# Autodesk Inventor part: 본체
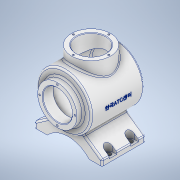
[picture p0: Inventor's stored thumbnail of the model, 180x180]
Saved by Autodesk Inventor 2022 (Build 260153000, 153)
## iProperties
Created: 2023-04
Part Number: 본체
Material: 알루미늄 6061
Document SubType Name: Modeling
Designer: Admin
Mass: 1296.38 g
Surface Area: 1061.17 cm^2
Volume: 480.141 cm^3
Density: 2.7 g/cm^3
Appearance: 알루미늄 - 평지
Author: Admin
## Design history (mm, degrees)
sketch "스케치5"
  geometry: L1 (0, -10.683)-(0, 64.095) reference; L2 (-86.8, 0)-(86.8, 0) reference; L3 (-62, 0)-(-62, 10); L4 (-62, 10)-(0, 53.413); L5 (0, 53.413)-(62, 10); L6 (62, 10)-(62, 0); L7 (-62, 0)-(62, 0); 1 further point
  constraints: 10 end point, 3 point on line, 2 perpendicular, 1 vertical
  dimensions: "d21" = 10 distance of L5.end L6.end; "d22" = 10 distance of L3.start L3.end; "d23" = 55 deg angle of L4 L3; "d24" = 55 deg angle of L6 L5; "d25" = 124 distance between parallel lines of L3 L6
extrude "돌출2" new body sketch "스케치5" stored distance "d26" = 80; taper "d27" = 0 deg
sketch "스케치6"
  geometry: L1 (77, 101)-(77, -97); L2 (0, -40)-(0, 40) reference; L3 (77, 60)-(113, 60); L4 (113, 60)-(113, 48); L5 (113, 48)-(127, 48); L6 (127, 48)-(127, -48.336); L7 (53.413, 40)-(10, 40) reference; A1 r 113 centre (77, 53) between (77, -60) and (127, -48.336); 1 further point
  constraints: 10 end point, 3 perpendicular, 3 point on line, 2 point on circle, 1 centre point, 1 horizontal, 1 vertical
  dimensions: "d28" = 77 distance between parallel lines of L2 L1; "d29" = 113 radius of A1; "d30" = 20 distance between parallel lines of L7 L3; "d31" = 72 diameter of L4 L1; "d32" = 100 diameter of L6 L1; "d33" = 12 distance of L3.end L4.end; "d34" = 120 distance from line of L3 A1.start
revolve "회전1" sketch "스케치6" stored, may be unused: angle "d35" = 90 deg
node "작업 평면1"
sketch "스케치7"
  geometry: L1 (0, -84)-(0, 84) reference; L2 (86.8, 0)-(-86.8, 0) reference; L3 (-36, 60)-(36, 60) reference; C1 r 36 at (0, -2); 1 further point
  constraints: 1 centre point, 1 point on line
  dimensions: "d37" = 72 diameter of C1; "d38" = 62 distance from line of L3 C1.centre
extrude "돌출3" join sketch "스케치7" stored distance "d39" = 80; taper "d40" = 0 deg
sketch "스케치8"
  geometry: C1 r 36 at (0, 0) reference; C2 r 27 at (0, 0); 1 further point
  constraints: 1 centre point, 1 coincident
  dimensions: "d41" = 54 diameter of C2
extrude "돌출4" cut sketch "스케치8" distance "d42" = 50; taper "d43" = 0 deg
sketch "스케치9"
  geometry: L1 (41, 60)-(113, 60) reference; L2 (77, 60)-(77, -67.76); L3 (77, 60)-(104, 60); L4 (104, 60)-(104, 41); L5 (104, 41)-(77, 41); L6 (77, 41)-(77, 60); L7 (77, 41)-(120, 41); L8 (120, 41)-(120, -43.887); L9 (77, -41)-(77, 41); L10 (127, 48)-(127, -48.336) reference; A1 r 113 centre (77, 53) between (27, -48.336) and (127, -48.336) reference; A2 r 106 centre (77, 53) between (77, -53) and (120, -43.887); 3 further points
  constraints: 16 end point, 3 parallel, 2 horizontal, 2 perpendicular, 2 point on circle, 1 centre point, 1 midpoint, 1 point on line, 1 vertical
  dimensions: "d46" = 7 radial gap between concentric circles of A1 A2; "d47" = 19 distance between parallel lines of L5 L1; "d48" = 86 diameter of L8 L2; "d49" = 54 diameter of L4 L2
revolve "회전2" sketch "스케치9" stored, may be unused: angle "d50" = 90 deg
sketch "스케치10" dims "d51" = 65
  geometry: L1 (0, 82)-(0, -86) reference; C1 r 27 at (0, 0) reference; 3 further points
  constraints: 1 coincident, 1 vertical alignment, 2 other
hole "구멍1" sketch "스케치10" at (0, 32.5) diameter "d52" = 3.242; stored, may be unused: countersink angle "d56" = 90 deg, drill point angle "d58" = 118 deg; dims "d53" = 8, "d54" = 4, "d55" = 2, "d57" = 10
sketch "스케치11" dims "d62" = 65
  geometry: L1 (0, -102.4)-(0, 75.4) reference; C1 r 36 at (0, 0) reference; 3 further points
  constraints: 1 coincident, 1 point on line, 1 vertical alignment, 2 other
hole "구멍2" sketch "스케치11" at (0, 32.5) diameter "d63" = 3.242; stored, may be unused: countersink angle "d67" = 90 deg, drill point angle "d69" = 118 deg; dims "d64" = 8, "d65" = 4, "d66" = 2, "d68" = 10
node "작업 평면2"
node "작업 평면3"
sketch "스케치14"
  geometry: L1 (41, 60)-(113, 60) reference; L2 (77, 60)-(77, -71); 2 further points
  constraints: 2 end point, 1 midpoint, 1 point on line, 1 vertical, 1 other
  dimensions: "d89" = 62 distance from line of L1 point (77, -2)
feature "엠보싱1" sketch "스케치14" dims "d28" = 77, "d29" = 113, "d30" = 20, "d31" = 72, "d32" = 100, "d33" = 12, "d34" = 120, "d90" = 0.5, "d91" = 0
sketch "스케치15"
  geometry: L1 (0, -28.4)-(0, 170.4) reference; L2 (-86.8, 0)-(86.8, 0) reference; L3 (62, 0)-(-62, 0) reference; L4 (-38.5, 0)-(38.5, 0); A1 r 52.096 centre (0, -35.096) between (38.5, 0) and (0, 17); A2 r 52.096 centre (0, -35.096) between (0, 17) and (-38.5, 0); 1 further point
  constraints: 4 point on circle, 2 centre point, 2 end point, 2 point on line, 1 collinear, 1 symmetric about line, 1 other
  dimensions: "d96" = 77 distance of L4.end L4.start; "d97" = 17 distance of point (0, 0) A1.end
extrude "돌출5" cut sketch "스케치15" extent not by distance; stored distance "d98" = 0; taper "d99" = 0 deg
node "작업 평면5"
sketch "스케치17"
  geometry: L1 (-62, -40)-(-62, 40) reference; L2 (62, -40)-(62, 40) reference; L3 (62, -40)-(26.694, -40) reference; 5 further points
  constraints: 2 horizontal alignment, 2 vertical alignment
  dimensions: "d106" = 8 distance from line of L1 point (-54, -20); "d107" = 8 distance from line of L2 point (54, -20); "d108" = 20 distance from line of L3 point (54, -20); "d109" = 40 distance of point (54, -20) point (54, 20)
hole "구멍4" sketch "스케치17" at (54, -20), (-54, -20), (-54, 20), (54, 20) diameter "d110" = 9; stored, may be unused: countersink angle "d114" = 90 deg, drill point angle "d116" = 0 deg; dims "d111" = 6, "d112" = 14, "d113" = 24, "d115" = 30
sketch "스케치18"
  geometry: L1 (0, 7)-(13, 7); L2 (0, -7)-(13, -7); L3 (13, -7)-(13, 7); L4 (0, 7)-(0, -7); L5 (-147.8, 20)-(39.8, 20) reference; L6 (-54, 104)-(-54, -64) reference; L7 (0, 33)-(13, 33); L8 (0, 33)-(0, 47); L9 (0, 47)-(13, 47); L10 (13, 47)-(13, 33); L11 (-121, 47)-(-121, 33); L12 (-108, 47)-(-121, 47); L13 (-108, 33)-(-108, 47); L14 (-108, 33)-(-121, 33); L15 (-108, 7)-(-121, 7); L16 (-121, -7)-(-121, 7); L17 (-108, -7)-(-121, -7); L18 (-108, 7)-(-108, -7); A1 r 7 centre (0, 0) between (0, 7) and (0, -7) reference; 1 further point
  constraints: 32 end point, 12 symmetric about line, 2 horizontal, 2 point on circle, 2 tangent, 2 vertical, 1 perpendicular
  dimensions: "d117" = 13 distance between parallel lines of L13 L11
extrude "돌출6" cut sketch "스케치18" extent not by distance; stored distance "d118" = 0; taper "d119" = 0 deg
fillet "모깎기1" dims "d120" = 3
fillet "모깎기2" dims "d121" = 3
chamfer "모따기1" distance "d122" = 1; stored, may be unused: second distance "d123" = 2, angle "d124" = 45 deg
fillet "모깎기3" dims "d125" = 3
fillet "모깎기4" dims "d126" = 3
node "솔리드2"
pattern_circular "원형 패턴1" dims angle "d60" = 360 deg
pattern_circular "원형 패턴2" dims angle "d71" = 360 deg
feature "A9D066F2-1C7D-4E18-AEED-F7BC21143FA4" dims "d110" = 9, "d111" = 6, "d112" = 14, "d113" = 24, "d114" = 90 deg, "d115" = 30, "d116" = 0
other parameters: "d36" = 142, "d73" = 45, "d88" = 314
